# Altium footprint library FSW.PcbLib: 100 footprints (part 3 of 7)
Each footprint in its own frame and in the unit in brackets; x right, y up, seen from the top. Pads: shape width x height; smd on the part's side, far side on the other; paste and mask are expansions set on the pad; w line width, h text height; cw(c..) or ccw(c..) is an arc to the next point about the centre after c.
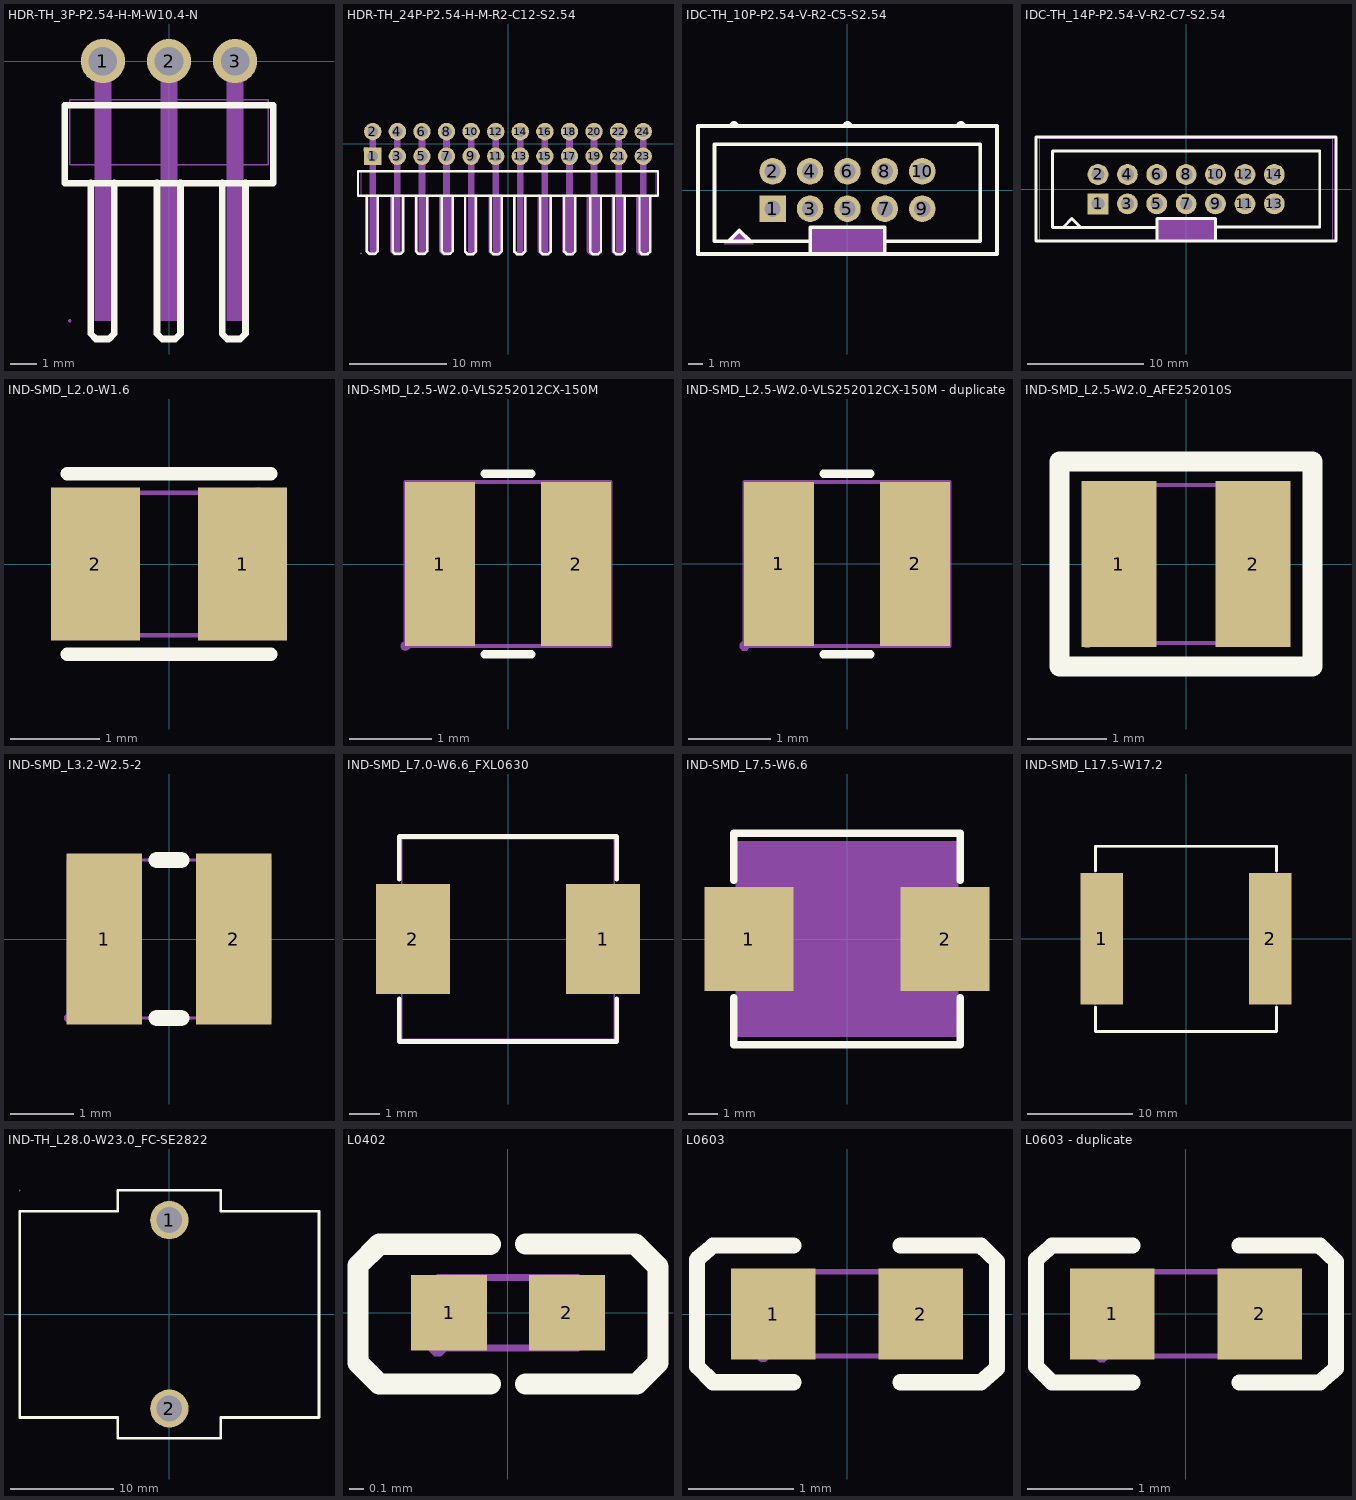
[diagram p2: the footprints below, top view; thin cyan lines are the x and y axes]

## HDR-TH_3P-P2.54-H-M-W10.4-N [mm]
pads (3):
  round 1.7 hole 1.1: 1(-2.54,0) 2(0,0) 3(2.54,0)
Top Overlay:
  lines w0.254: -3.01,-4.68 -3.01,-10.48 -2.81,-10.68 -2.31,-10.68 -2.11,-10.48 -2.11,-4.68 ; -0.46,-4.68 -0.46,-10.48 -0.26,-10.68 0.24,-10.68 0.44,-10.48 0.44,-4.68 ; 2.04,-4.68 2.04,-10.48 2.24,-10.68 2.74,-10.68 2.94,-10.48 2.94,-4.68 ; -4.01,-4.7 4.01,-4.7 4.01,-1.7 -4.01,-1.7 -4.01,-4.7
Mechanical 2:
  region: -2.86,-4.71 -2.86,-9.98 -2.22,-9.98 -2.22,-4.71
  region: -0.32,-4.71 -0.32,-9.98 0.32,-9.98 0.32,-4.71
  region: 2.22,-4.71 2.22,-9.98 2.86,-9.98 2.86,-4.71
Mechanical 6:
  lines w0.051: -3.81,-3.98 -3.81,-1.48 3.81,-1.48 3.81,-3.98 -3.81,-3.98
Mechanical 7:
  region: -2.86,0.32 -2.22,0.32 -2.22,-9.98 -2.86,-9.98
  region: -0.32,0.32 0.32,0.32 0.32,-9.98 -0.32,-9.98
  region: 2.22,0.32 2.86,0.32 2.86,-9.98 2.22,-9.98
Mechanical 8:
  region: -3.75,-9.98 -3.75,-10.005 -3.785,-10.04 -3.835,-10.04 -3.87,-10.005 -3.87,-9.98 -3.87,-9.955 -3.835,-9.92 -3.785,-9.92 -3.75,-9.955 -3.75,-9.98
Mechanical 9:
  region: 2.22,0.32 2.86,0.32 2.86,-0.32 2.22,-0.32
  region: -2.86,0.32 -2.22,0.32 -2.22,-0.32 -2.86,-0.32
  region: -0.32,0.32 0.32,0.32 0.32,-0.32 -0.32,-0.32
3D body "HDR-TH_3P-P2.54-H-M-W10.4-N.step": height 2.75, standoff -2.75, extent -4.064,-9.899 3.566,0.401

## HDR-TH_24P-P2.54-H-M-R2-C12-S2.54 [mm]
pads (24):
  rect 1.778x1.8 hole 1.1: 1(-13.97,-1.27)
  round 1.8 hole 1.1: 2(-13.97,1.27) 3(-11.43,-1.27) 4(-11.43,1.27) 5(-8.89,-1.27) 6(-8.89,1.27) 7(-6.35,-1.27) 8(-6.35,1.27) 9(-3.81,-1.27) 10(-3.81,1.27) 11(-1.27,-1.27) 12(-1.27,1.27) 13(1.27,-1.27) 14(1.27,1.27) 15(3.81,-1.27) 16(3.81,1.27) 17(6.35,-1.27) 18(6.35,1.27) 19(8.89,-1.27) 20(8.89,1.27) 21(11.43,-1.27) 22(11.43,1.27) 23(13.97,-1.27) 24(13.97,1.27)
Top Overlay:
  lines w0.254: -14.577,-5.35 -14.577,-11.096 -14.323,-11.35 -13.739,-11.35 -13.46,-11.071 -13.46,-5.35 ; -11.92,-5.35 -11.92,-11.096 -11.666,-11.35 -11.082,-11.35 -10.802,-11.071 -10.802,-5.35 ; -9.48,-5.36 -9.48,-11.106 -9.226,-11.36 -8.642,-11.36 -8.362,-11.081 -8.362,-5.36 ; -6.822,-5.36 -6.822,-11.106 -6.568,-11.36 -5.984,-11.36 -5.705,-11.081 -5.705,-5.36 ; -4.44,-5.37 -4.44,-11.116 -4.186,-11.37 -3.602,-11.37 -3.322,-11.091 -3.322,-5.37 ; -1.783,-5.37 -1.783,-11.116 -1.529,-11.37 -0.944,-11.37 -0.665,-11.091 -0.665,-5.37 ; 0.658,-5.38 0.658,-11.126 0.912,-11.38 1.496,-11.38 1.775,-11.101 1.775,-5.38 ; 3.315,-5.38 3.315,-11.126 3.569,-11.38 4.153,-11.38 4.433,-11.101 4.433,-5.38 ; 5.83,-5.37 5.83,-11.116 6.084,-11.37 6.668,-11.37 6.948,-11.091 6.948,-5.37 ; 8.487,-5.37 8.487,-11.116 8.741,-11.37 9.326,-11.37 9.605,-11.091 9.605,-5.37 ; 10.928,-5.38 10.928,-11.126 11.182,-11.38 11.766,-11.38 12.045,-11.101 12.045,-5.38 ; 13.585,-5.38 13.585,-11.126 13.839,-11.38 14.423,-11.38 14.703,-11.101 14.703,-5.38 ; -15.494,-5.35 -15.4,-5.35 15.494,-5.35 15.494,-2.81 -15.494,-2.81 -15.494,-5.35
Mechanical 2:
  drawing of 13 lines, arcs and shapes, not listed
Mechanical 6:
  lines w0.051: -15.18,-5.31 -15.18,-2.81 15.3,-2.81 15.3,-5.31 -15.18,-5.31
Mechanical 7:
  region: 14.29,-11.31 13.65,-11.31 13.65,1.59 14.29,1.59
  region: 11.75,-11.31 11.11,-11.31 11.11,1.59 11.75,1.59
  region: 9.21,-11.31 8.57,-11.31 8.57,1.59 9.21,1.59
  region: 6.67,-11.31 6.03,-11.31 6.03,1.59 6.67,1.59
  region: 4.13,-11.31 3.49,-11.31 3.49,1.59 4.13,1.59
  region: 1.59,-11.31 0.95,-11.31 0.95,1.59 1.59,1.59
  region: -13.65,-11.31 -14.29,-11.31 -14.29,1.59 -13.65,1.59
  region: -11.11,-11.31 -11.75,-11.31 -11.75,1.59 -11.11,1.59
  region: -8.57,-11.31 -9.21,-11.31 -9.21,1.59 -8.57,1.59
  region: -6.03,-11.31 -6.67,-11.31 -6.67,1.59 -6.03,1.59
  region: -3.49,-11.31 -4.13,-11.31 -4.13,1.59 -3.49,1.59
  region: -0.95,-11.31 -1.59,-11.31 -1.59,1.59 -0.95,1.59
Mechanical 8:
  region: -15.12,-11.31 -15.12,-11.335 -15.155,-11.37 -15.205,-11.37 -15.24,-11.335 -15.24,-11.31 -15.24,-11.285 -15.205,-11.25 -15.155,-11.25 -15.12,-11.285 -15.12,-11.31
Mechanical 9:
  region: 14.29,0.95 13.65,0.95 13.65,1.59 14.29,1.59
  region: 14.29,-1.59 13.65,-1.59 13.65,-0.95 14.29,-0.95
  region: 11.75,0.95 11.11,0.95 11.11,1.59 11.75,1.59
  region: 11.75,-1.59 11.11,-1.59 11.11,-0.95 11.75,-0.95
  region: 9.21,0.95 8.57,0.95 8.57,1.59 9.21,1.59
  region: 9.21,-1.59 8.57,-1.59 8.57,-0.95 9.21,-0.95
  region: 6.67,0.95 6.03,0.95 6.03,1.59 6.67,1.59
  region: 6.67,-1.59 6.03,-1.59 6.03,-0.95 6.67,-0.95
  region: 4.13,0.95 3.49,0.95 3.49,1.59 4.13,1.59
  region: 4.13,-1.59 3.49,-1.59 3.49,-0.95 4.13,-0.95
  region: 1.59,0.95 0.95,0.95 0.95,1.59 1.59,1.59
  region: 1.59,-1.59 0.95,-1.59 0.95,-0.95 1.59,-0.95
  region: -0.95,0.95 -1.59,0.95 -1.59,1.59 -0.95,1.59
  region: -0.95,-1.59 -1.59,-1.59 -1.59,-0.95 -0.95,-0.95
  region: -3.49,0.95 -4.13,0.95 -4.13,1.59 -3.49,1.59
  region: -3.49,-1.59 -4.13,-1.59 -4.13,-0.95 -3.49,-0.95
  region: -6.03,0.95 -6.67,0.95 -6.67,1.59 -6.03,1.59
  region: -6.03,-1.59 -6.67,-1.59 -6.67,-0.95 -6.03,-0.95
  region: -8.57,0.95 -9.21,0.95 -9.21,1.59 -8.57,1.59
  region: -8.57,-1.59 -9.21,-1.59 -9.21,-0.95 -8.57,-0.95
  region: -11.11,0.95 -11.75,0.95 -11.75,1.59 -11.11,1.59
  region: -11.11,-1.59 -11.75,-1.59 -11.75,-0.95 -11.11,-0.95
  region: -13.65,0.95 -14.29,0.95 -14.29,1.59 -13.65,1.59
  region: -13.65,-1.59 -14.29,-1.59 -14.29,-0.95 -13.65,-0.95
3D body "HDR-TH_24P-P2.54-H-M-R2-C12-S2.54.step": height 5, standoff -3, extent -15.24,-11.314 15.25,1.586

## IDC-TH_10P-P2.54-V-R2-C5-S2.54 [mm]
pads (10):
  rect 1.8x1.8 hole 1.1: 1(-5.08,-1.27)
  round 1.8 hole 1.1: 2(-5.08,1.27) 3(-2.54,-1.27) 4(-2.54,1.27) 5(0,-1.27) 6(0,1.27) 7(2.54,-1.27) 8(2.54,1.27) 9(5.08,-1.27) 10(5.08,1.27)
Top Overlay:
  lines w0.254: -9.017,3.093 -9.017,-3.477 -2.529,-3.477 ; -9.008,3.102 9.008,3.102 ; -7.976,-3.375 -7.341,-2.74 -6.655,-3.426 -6.655,-3.451 ; -7.9,4.349 cw(c-7.7,4.349) -7.5,4.349 ; -2.529,-4.35 -2.529,-2.521 2.54,-2.521 2.54,-4.35 ; -0.2,4.349 cw(c0,4.349) 0.2,4.349 ; 2.54,-3.477 5.08,-3.477 9.008,-3.477 9.008,3.093 ; 7.5,4.349 cw(c7.7,4.349) 7.9,4.349 ; -10.15,-4.35 10.15,-4.35 10.15,4.35 -10.15,4.35 -10.15,-4.35
Mechanical 2:
  region: -2.54,-4.35 -2.54,-2.445 2.54,-2.445 2.54,-4.35
  region: -8.382,-3.683 -7.366,-2.667 -6.35,-3.683
Mechanical 6:
  lines w0.051: -10.15,-4.35 10.15,-4.35 10.15,4.35 -10.15,4.35 -10.15,-4.35
Mechanical 8:
  region: -10.089,-4.35 -10.089,-4.375 -10.125,-4.411 -10.175,-4.411 -10.211,-4.375 -10.211,-4.35 -10.211,-4.325 -10.175,-4.289 -10.125,-4.289 -10.089,-4.325 -10.089,-4.35 -10.09,-4.35
Mechanical 9:
  region: -5.4,-0.95 -4.76,-0.95 -4.76,-1.59 -5.4,-1.59
  region: -5.4,1.59 -4.76,1.59 -4.76,0.95 -5.4,0.95
  region: -2.86,-0.95 -2.22,-0.95 -2.22,-1.59 -2.86,-1.59
  region: -2.86,1.59 -2.22,1.59 -2.22,0.95 -2.86,0.95
  region: -0.32,-0.95 0.32,-0.95 0.32,-1.59 -0.32,-1.59
  region: -0.32,1.59 0.32,1.59 0.32,0.95 -0.32,0.95
  region: 2.22,-0.95 2.86,-0.95 2.86,-1.59 2.22,-1.59
  region: 2.22,1.59 2.86,1.59 2.86,0.95 2.22,0.95
  region: 4.76,-0.95 5.4,-0.95 5.4,-1.59 4.76,-1.59
  region: 4.76,1.59 5.4,1.59 5.4,0.95 4.76,0.95

## IDC-TH_14P-P2.54-V-R2-C7-S2.54 [mm]
pads (14):
  rect 1.8x1.8 hole 1.1: 1(-7.62,-1.27)
  round 1.8 hole 1.1: 2(-7.62,1.27) 3(-5.08,-1.27) 4(-5.08,1.27) 5(-2.54,-1.27) 6(-2.54,1.27) 7(0,-1.27) 8(0,1.27) 9(2.54,-1.27) 10(2.54,1.27) 11(5.08,-1.27) 12(5.08,1.27) 13(7.62,-1.27) 14(7.62,1.27)
Top Overlay:
  lines w0.254: -12.979,-4.479 -12.979,4.521 ; -12.951,4.521 12.951,4.521 12.951,-4.479 ; -12.926,-4.496 12.951,-4.496 ; -11.557,-3.302 -2.54,-3.302 ; -11.557,-3.277 -11.557,3.293 ; -11.548,3.302 11.548,3.302 ; -10.516,-3.175 -9.881,-2.54 -9.195,-3.226 -9.195,-3.251 ; -2.518,-4.496 -2.518,-2.54 2.54,-2.54 2.54,-4.496 ; 2.54,-3.277 11.548,-3.277 11.548,3.293
Mechanical 2:
  region: -2.5,-4.4 -2.5,-2.5 2.6,-2.5 2.6,-4.4
Mechanical 6:
  lines w0.051: -12.65,-4.4 -12.65,4.4 12.65,4.4 12.65,-4.4 -12.65,-4.4
Mechanical 8:
  region: -12.589,-4.4 -12.589,-4.425 -12.625,-4.461 -12.675,-4.461 -12.711,-4.425 -12.711,-4.4 -12.711,-4.375 -12.675,-4.339 -12.625,-4.339 -12.589,-4.375 -12.589,-4.4 -12.59,-4.4
Mechanical 9:
  region: -7.94,-0.95 -7.3,-0.95 -7.3,-1.59 -7.94,-1.59
  region: -7.94,1.59 -7.3,1.59 -7.3,0.95 -7.94,0.95
  region: -5.4,-0.95 -4.76,-0.95 -4.76,-1.59 -5.4,-1.59
  region: -5.4,1.59 -4.76,1.59 -4.76,0.95 -5.4,0.95
  region: -2.86,-0.95 -2.22,-0.95 -2.22,-1.59 -2.86,-1.59
  region: -2.86,1.59 -2.22,1.59 -2.22,0.95 -2.86,0.95
  region: -0.32,-0.95 0.32,-0.95 0.32,-1.59 -0.32,-1.59
  region: -0.32,1.59 0.32,1.59 0.32,0.95 -0.32,0.95
  region: 2.22,-0.95 2.86,-0.95 2.86,-1.59 2.22,-1.59
  region: 2.22,1.59 2.86,1.59 2.86,0.95 2.22,0.95
  region: 4.76,-0.95 5.4,-0.95 5.4,-1.59 4.76,-1.59
  region: 4.76,1.59 5.4,1.59 5.4,0.95 4.76,0.95
  region: 7.3,-0.95 7.94,-0.95 7.94,-1.59 7.3,-1.59
  region: 7.3,1.59 7.94,1.59 7.94,0.95 7.3,0.95

## IND-SMD_L2.0-W1.6 [mm]
pads (2):
  rect 1x1.72 smd: 1(0.828,0) 2(-0.828,0)
Top Overlay:
  lines w0.152: -1.143,-1.016 1.143,-1.016 ; -1.143,1.016 1.143,1.016
Mechanical 6:
  lines w0.051: -1,-0.8 -1,0.8 1,0.8 1,-0.8 -1,-0.8
Mechanical 8:
  region: 1.06,0.8 1.06,0.775 1.025,0.74 0.975,0.74 0.94,0.775 0.94,0.8 0.94,0.825 0.975,0.86 1.025,0.86 1.06,0.825 1.06,0.8
Mechanical 9:
  region: 0.4,0.8 1,0.8 1,-0.8 0.4,-0.8
  region: -1,0.8 -0.4,0.8 -0.4,-0.8 -1,-0.8
3D body "IND-SMD_L2.0-W1.6.step": height 1.11, standoff -0.01, extent -1.016,-0.838 1.004,0.762

## IND-SMD_L2.5-W2.0-VLS252012CX-150M [mil]
pads (2):
  rect 33.5x78.7 smd: 1(-32.7,0) 2(32.7,0)
Top Overlay:
  lines w4: -11.3,-43.3 11.3,-43.3 ; -11.3,43.3 11.3,43.3
Mechanical 6:
  lines w2: -49.2,-39.4 49.2,-39.4 49.2,39.4 -49.2,39.4 -49.2,-39.4
Mechanical 8:
  region: -46.9,-39.4 -47.3,-40.6 -48.3,-41.5 -49.6,-41.7 -50.8,-41.1 -51.5,-40 -51.5,-38.7 -50.8,-37.6 -49.6,-37 -48.3,-37.2 -47.3,-38.1
Mechanical 9:
  region: 16.9,39.4 48.4,39.4 48.4,-39.4 16.9,-39.4
  region: -48.5,39.4 -17,39.4 -17,-39.4 -48.5,-39.4
3D body "IND-SMD_L2.5-W2.0-VLS252012CX-150M.step": height 47.2, standoff -0.47, extent -49.25,-39.41 49.25,39.41

## IND-SMD_L2.5-W2.0-VLS252012CX-150M - duplicate [mm]
pads (2):
  rect 0.85x2 smd: 1(-0.83,0) 2(0.83,0)
Top Overlay:
  lines w0.102: -0.288,-1.1 0.287,-1.1 ; -0.288,1.1 0.287,1.1
Mechanical 6:
  lines w0.051: -1.25,-1 1.25,-1 1.25,1 -1.25,1 -1.25,-1
Mechanical 8:
  region: -1.19,-1 -1.19,-1.025 -1.225,-1.06 -1.275,-1.06 -1.31,-1.025 -1.31,-1 -1.31,-0.975 -1.275,-0.94 -1.225,-0.94 -1.19,-0.975 -1.19,-1
Mechanical 9:
  region: 0.43,1 1.23,1 1.23,-1 0.43,-1
  region: -1.23,1 -0.43,1 -0.43,-1 -1.23,-1

## IND-SMD_L2.5-W2.0_AFE252010S [mm]
pads (2):
  rect 0.95x2.1 smd: 1(-0.85,0) 2(0.85,0)
Top Overlay:
  lines w0.254: -1.6,-1.3 -1.6,1.3 1.6,1.3 1.6,-1.3 -1.6,-1.3
Mechanical 6:
  lines w0.051: -1.25,-1 1.25,-1 1.25,1 -1.25,1 -1.25,-1
Mechanical 8:
  region: -1.19,-1 -1.19,-1.025 -1.225,-1.06 -1.275,-1.06 -1.31,-1.025 -1.31,-1 -1.31,-0.975 -1.275,-0.94 -1.225,-0.94 -1.19,-0.975 -1.19,-1
Mechanical 9:
  region: 0.45,1 1.25,1 1.25,-1 0.45,-1
  region: -1.25,1 -0.45,1 -0.45,-1 -1.25,-1

## IND-SMD_L3.2-W2.5-2 [mm]
pads (2):
  rect 1.2x2.7 smd: 1(-1.025,0) 2(1.025,0)
Top Overlay:
  lines w0.254: -0.194,-1.25 0.194,-1.25 ; -0.194,1.25 0.194,1.25
Mechanical 6:
  lines w0.051: -1.6,-1.25 1.6,-1.25 1.6,1.25 -1.6,1.25 -1.6,-1.25
Mechanical 8:
  region: -1.54,-1.25 -1.54,-1.275 -1.575,-1.31 -1.625,-1.31 -1.66,-1.275 -1.66,-1.25 -1.66,-1.225 -1.625,-1.19 -1.575,-1.19 -1.54,-1.225 -1.54,-1.25
Mechanical 9:
  region: -1.6,1.25 -0.45,1.25 -0.45,-1.25 -1.6,-1.25
  region: 0.45,1.25 1.6,1.25 1.6,-1.25 0.45,-1.25
3D body "IND-SMD_L3.2-W2.5-2.step": height 2.03, standoff 0.03, extent -1.6,-1.378 1.6,1.123

## IND-SMD_L7.0-W6.6_FXL0630 [mil]
pads (2):
  rect 95.4x142.5 smd: 1(123.1,0) 2(-123.2,0)
Top Overlay:
  lines w6: -140.8,-77.2 -140.8,-132.9 140.8,-132.9 140.8,-77.2 ; -140.8,77.3 -140.8,132.9 140.8,132.9 140.8,77.3
Mechanical 6:
  lines w2: -137.8,-129.9 137.8,-129.9 137.8,129.9 -137.8,129.9 -137.8,-129.9
Mechanical 8:
  region: 140.1,129.9 139.7,128.7 138.7,127.8 137.4,127.6 136.2,128.2 135.5,129.3 135.5,130.6 136.2,131.7 137.4,132.3 138.7,132.1 139.7,131.2
Mechanical 9:
  region: 137.8,-63 137.8,63 78.7,63 78.7,-63
  region: -137.8,-63 -137.8,63 -78.8,63 -78.8,-63

## IND-SMD_L7.5-W6.6 [mm]
pads (2):
  rect 3x3.5 smd paste+0 mask+0.051: 1(-3.302,0) 2(3.302,0)
Top Overlay:
  lines w0.254: -3.81,-1.981 -3.81,-3.556 3.81,-3.556 3.81,-1.981 ; -3.81,1.981 -3.81,3.556 3.81,3.556 3.81,1.981
Mechanical 9:
  region: -3.75,3.3 3.75,3.3 3.75,-3.3 -3.75,-3.3
Mechanical 11:
  region: -3.72,-3.3 -3.729,-3.279 -3.75,-3.27 -3.771,-3.279 -3.78,-3.3 -3.771,-3.321 -3.75,-3.33 -3.729,-3.321
Mechanical 12:
  region: 3.75,-1.5 1.802,-1.5 1.802,1.5 3.75,1.5
  region: -3.75,1.5 -1.802,1.5 -1.802,-1.5 -3.75,-1.5

## IND-SMD_L17.5-W17.2 [mil]
pads (2):
  rect 157.5x492.1 smd: 1(-315,0) 2(315,0)
Top Overlay:
  lines w10: -338.6,-255.2 -338.6,-284.7 -338.6,-346.5 338.6,-346.5 338.6,-284.7 ; -338.6,255.1 -338.6,284.6 -338.6,346.4 338.6,346.4 338.6,284.6 ; 338.6,-290.4 338.6,-255.2 ; 338.6,255.1 338.6,289.6
Mechanical 3:
  lines w2: -338.6,-344.5 -338.6,344.4 338.6,344.4 338.6,-344.5 -338.6,-344.5
Mechanical 5:
  region: -336.2,-344.5 -336.6,-345.8 -337.6,-346.7 -338.9,-346.9 -340.1,-346.3 -340.8,-345.2 -340.8,-343.9 -340.1,-342.8 -338.9,-342.2 -337.6,-342.4 -336.6,-343.3
Mechanical 6:
  region: 240.2,235 338.6,235 338.6,-235.1 240.2,-235.1
  region: -338.6,235 -240.2,235 -240.2,-235.1 -338.6,-235.1

## IND-TH_L28.0-W23.0_FC-SE2822 [mm]
pads (2):
  round 3.7 hole 2.5: 1(0,9.125) 2(0,-9.125)
Top Overlay:
  lines w0.254: -14.5,-10 -5,-10 -5,-12 5,-12 5,-10 14.5,-10 14.5,10 5,10 5,12 -5,12 -5,10 -14.5,10 -14.5,-10
Mechanical 6:
  lines w0.051: -14.5,-10 -5,-10 -5,-12 5,-12 5,-10 14.5,-10 14.5,10 5,10 5,12 -5,12 -5,10 -14.5,10 -14.5,-10
Mechanical 8:
  region: -14.439,12 -14.439,11.975 -14.475,11.939 -14.525,11.939 -14.561,11.975 -14.561,12 -14.561,12.025 -14.525,12.061 -14.475,12.061 -14.439,12.025 -14.439,12 -14.44,12
Mechanical 9:
  region: 1.151,-9.125 1.151,-9.276 1.072,-9.569 0.921,-9.831 0.706,-10.046 0.444,-10.197 0.151,-10.276 -0.151,-10.276 -0.444,-10.197 -0.706,-10.046 -0.921,-9.831 -1.072,-9.569 -1.151,-9.276 -1.151,-9.125 -1.151,-8.973 -1.072,-8.681 -0.921,-8.418 -0.706,-8.204 -0.444,-8.053 -0.151,-7.974 0.151,-7.974 0.444,-8.053 0.706,-8.204 0.921,-8.418 1.072,-8.681 1.151,-8.973 1.151,-9.125 1.15,-9.125
  region: 1.151,9.125 1.151,8.974 1.072,8.681 0.921,8.419 0.706,8.204 0.444,8.053 0.151,7.974 -0.151,7.974 -0.444,8.053 -0.706,8.204 -0.921,8.419 -1.072,8.681 -1.151,8.974 -1.151,9.125 -1.151,9.276 -1.072,9.569 -0.921,9.831 -0.706,10.046 -0.444,10.197 -0.151,10.276 0.151,10.276 0.444,10.197 0.706,10.046 0.921,9.831 1.072,9.569 1.151,9.276 1.151,9.125 1.15,9.125

## L0402 [mm]
pads (2):
  rect 0.54x0.54 smd: 1(-0.42,0) 2(0.42,0)
Top Overlay:
  lines w0.152: -0.127,-0.508 -0.917,-0.508 -1.069,-0.356 -1.069,0.337 -0.917,0.489 -0.127,0.489 ; 0.127,-0.508 0.917,-0.508 1.069,-0.356 1.069,0.328 0.907,0.49 0.127,0.49
Mechanical 6:
  lines w0.051: -0.5,-0.25 -0.5,0.25 0.5,0.25 0.5,-0.25 -0.5,-0.25
Mechanical 8:
  region: -0.44,-0.25 -0.44,-0.275 -0.475,-0.31 -0.525,-0.31 -0.56,-0.275 -0.56,-0.25 -0.56,-0.225 -0.525,-0.19 -0.475,-0.19 -0.44,-0.225 -0.44,-0.25
Mechanical 9:
  region: -0.5,-0.25 -0.5,0.25 -0.25,0.25 -0.25,-0.25
  region: 0.5,-0.25 0.5,0.25 0.25,0.25 0.25,-0.25
3D body "L0402.step": height 0.5, standoff 0, extent -0.5,-0.25 0.5,0.25

## L0603 [mil]
pads (2):
  rect 31.5x34 smd paste-3937 mask+2: 1(-27.6,0) 2(27.5,0)
Top Overlay:
  lines w6: -50.1,-25.5 -20.1,-25.5 ; -50.1,25.6 -20.1,25.6 ; -50,-25.6 -56.1,-19.6 -56.1,20.4 -50,25.6 ; 20,-25.5 50,-25.5 56,-20.3 56,19.7 50,25.6 20,25.6
Top Paste:
  region: -9.9,5.7 -9.9,-5.2 -20.7,-16.8 -40.5,-16.8 -43.1,-14.3 -43.1,14.7 -40.5,17.2 -20.7,17.2
  region: 10.4,6.1 10.4,-4.8 21.2,-16.3 41,-16.3 43.5,-13.8 43.5,15.2 41,17.7 21.2,17.7
Mechanical 6:
  lines w2: -31.5,-15.7 31.5,-15.7 31.5,15.8 -31.5,15.8 -31.5,-15.7
Mechanical 8:
  region: -29.2,-15.7 -29.5,-17 -30.5,-17.9 -31.9,-18 -33.1,-17.5 -33.8,-16.4 -33.8,-15 -33.1,-13.9 -31.9,-13.4 -30.5,-13.6 -29.5,-14.4
Mechanical 9:
  region: 31.5,-15.7 19.6,-15.7 19.6,15.8 31.5,15.8
  region: -19.7,-15.7 -31.5,-15.7 -31.5,15.8 -19.7,15.8
3D body "L0603.step": height 19.84, standoff 0.16, extent -31.5,-15.75 31.5,15.75

## L0603 - duplicate [mm]
pads (2):
  rect 0.8x0.864 smd paste-100 mask+0.051: 1(-0.7,0) 2(0.7,0)
Top Overlay:
  lines w0.152: -1.272,-0.65 -0.51,-0.65 ; -1.272,0.65 -0.51,0.65 ; -1.27,-0.651 -1.424,-0.499 -1.424,0.517 -1.27,0.65 ; 0.51,-0.65 1.272,-0.65 ; 0.51,0.65 1.272,0.65 ; 1.27,-0.65 1.424,-0.517 1.424,0.499 1.27,0.65
Top Paste:
  region: -0.252,0.143 -0.252,-0.134 -0.526,-0.427 -1.029,-0.427 -1.093,-0.363 -1.093,0.373 -1.029,0.437 -0.526,0.437
  region: 0.264,0.154 0.264,-0.122 0.538,-0.416 1.042,-0.416 1.106,-0.352 1.106,0.384 1.042,0.448 0.538,0.448
Mechanical 6:
  lines w0.051: -0.8,-0.4 0.8,-0.4 0.8,0.4 -0.8,0.4 -0.8,-0.4
Mechanical 8:
  region: -0.74,-0.4 -0.74,-0.425 -0.775,-0.46 -0.825,-0.46 -0.86,-0.425 -0.86,-0.4 -0.86,-0.375 -0.825,-0.34 -0.775,-0.34 -0.74,-0.375 -0.74,-0.4
Mechanical 9:
  region: 0.8,-0.4 0.5,-0.4 0.5,0.4 0.8,0.4
  region: -0.5,-0.4 -0.8,-0.4 -0.8,0.4 -0.5,0.4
